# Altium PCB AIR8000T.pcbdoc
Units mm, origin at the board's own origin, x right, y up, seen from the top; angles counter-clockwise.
Board outline 36.51 x 36.8 mm, 2 copper layers (Top Layer, Bottom Layer); 1 components, 0 nets, 104 pads, 0 vias.
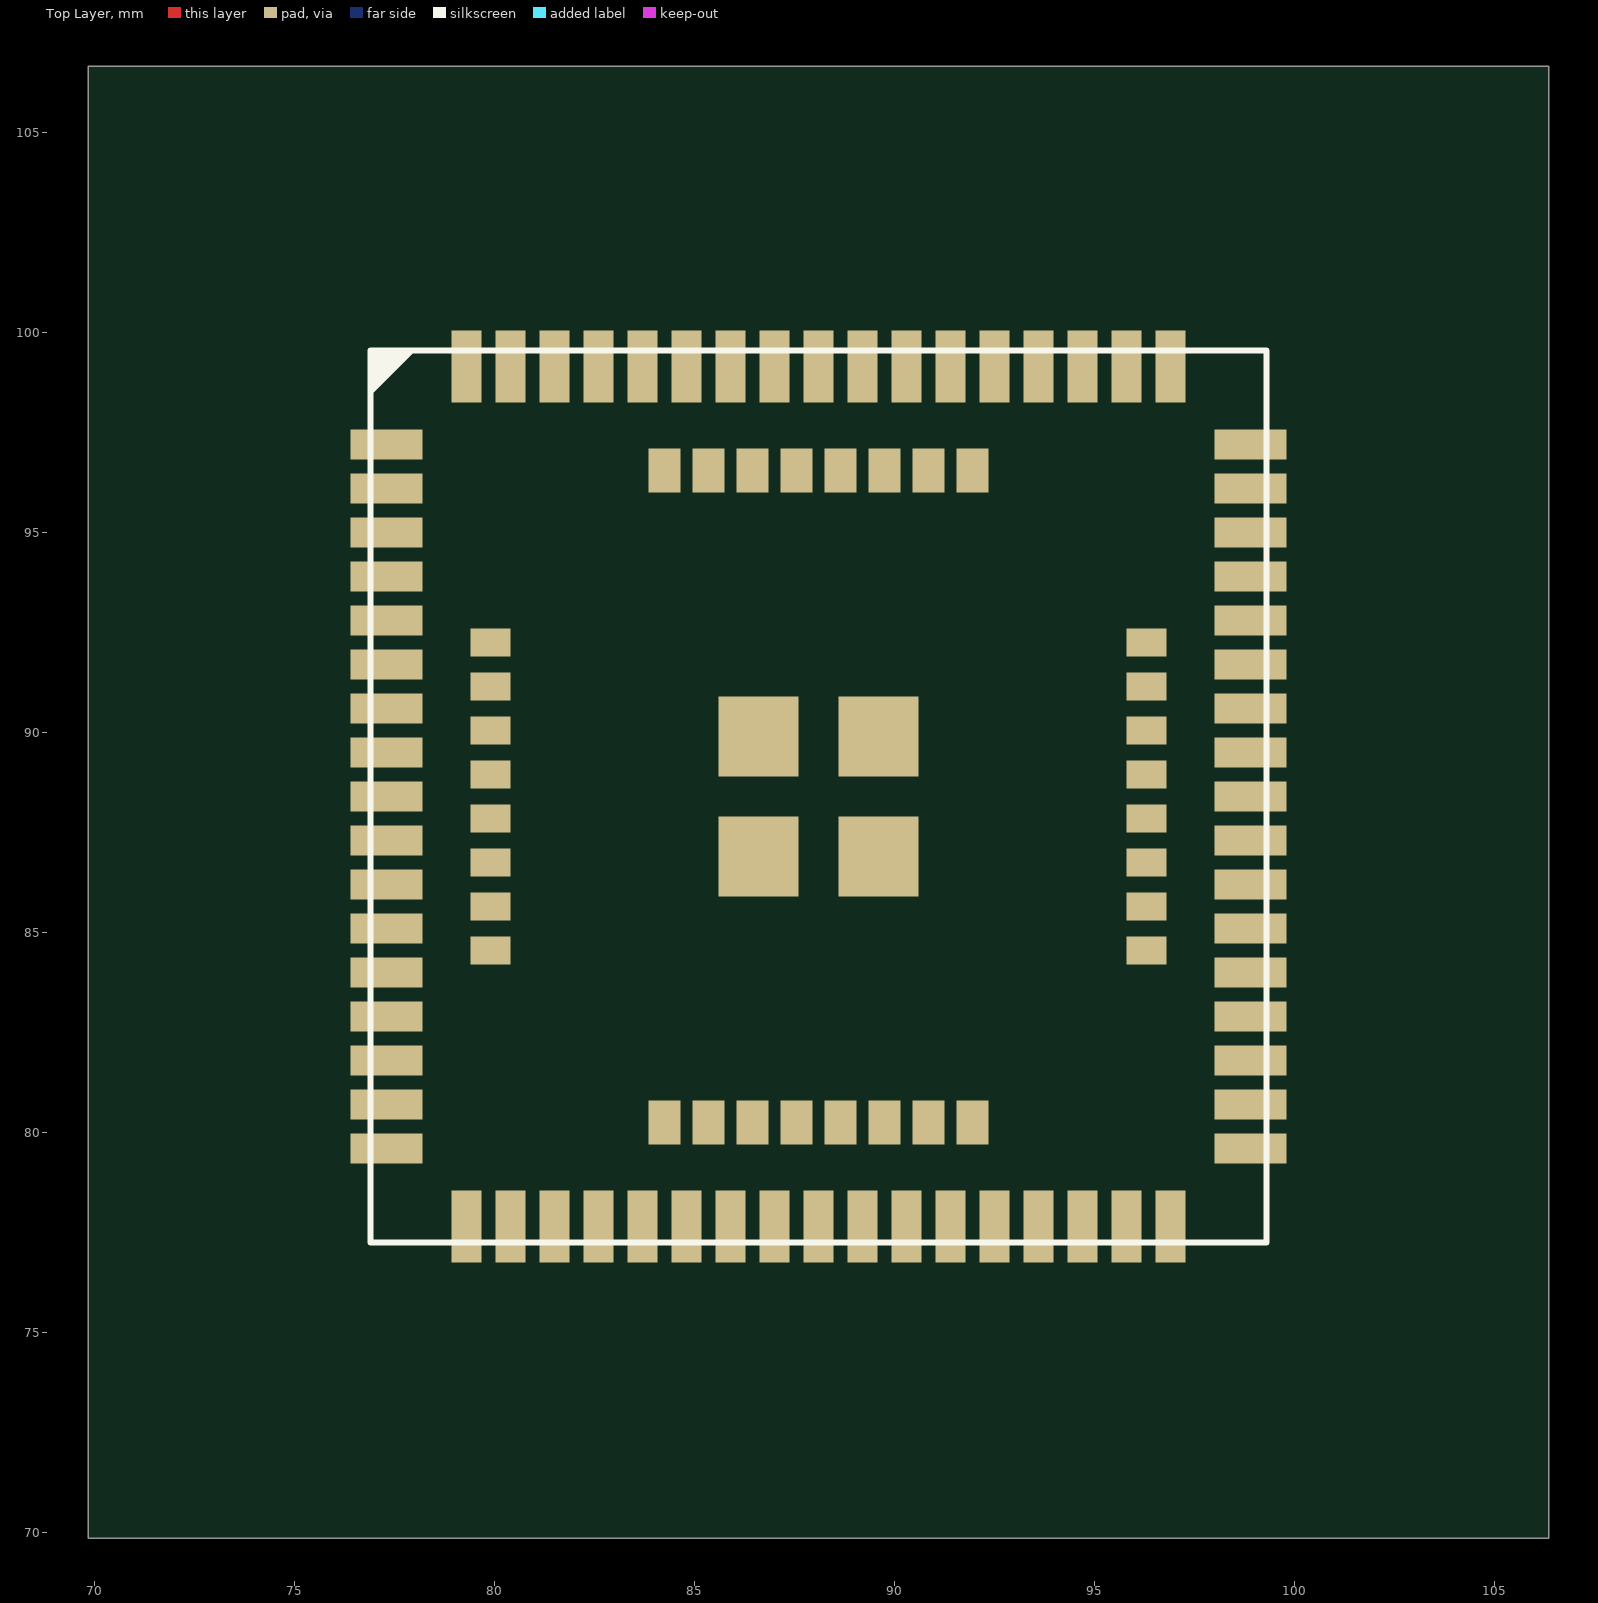
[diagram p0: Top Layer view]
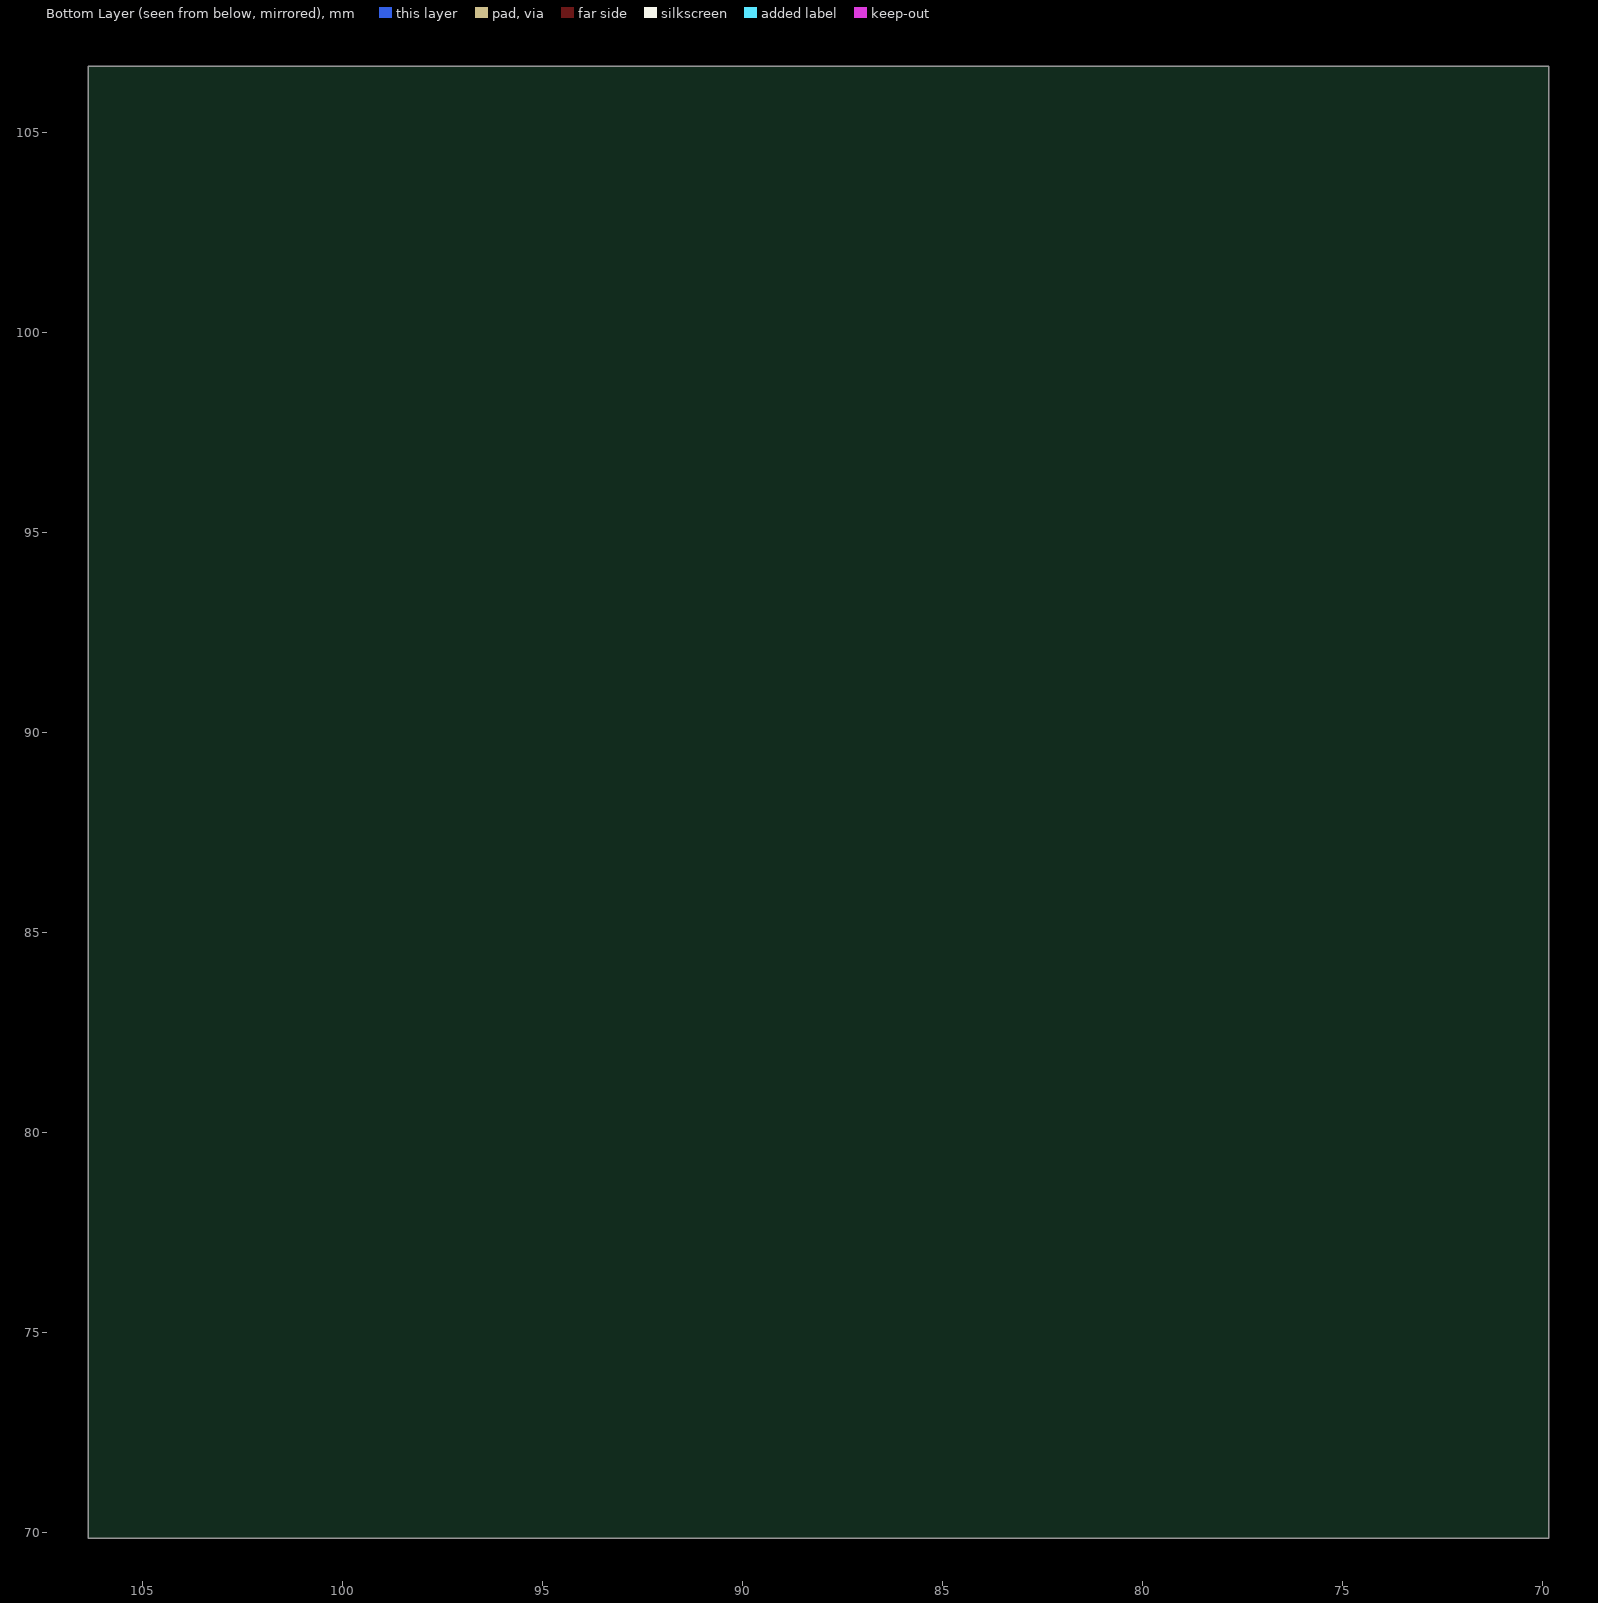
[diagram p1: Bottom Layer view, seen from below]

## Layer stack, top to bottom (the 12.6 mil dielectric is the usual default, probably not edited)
Top Layer: signal copper (thickness not stored)
Dielectric: dielectric 0.32, FR-4, Dk 4.8
Bottom Layer: signal copper (thickness not stored)

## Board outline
106.357,69.85 69.85,69.85 69.85,106.65 106.357,106.65

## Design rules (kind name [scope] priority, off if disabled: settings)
BoardOutlineClearance safeClearance [All] p0: genericclearance=0.254 ignorepadtopadclearanceinfootprint=FALSE except(0: Arc-SplitContinuation Track-SplitContinuation SMDPad-SplitContinuation THPad-SplitContinuation Via-SplitContinuation Fill-SplitContinuation Poly-SplitContinuation Region-SplitContinuation Text-SplitContinuation; 0.152: Track-CutoutEdge SMDPad-CutoutEdge THPad-CutoutEdge Via-CutoutEdge Fill-CutoutEdge Region-CutoutEdge; 0.3: Track-OutlineEdge SMDPad-OutlineEdge THPad-OutlineEdge Via-OutlineEdge Fill-OutlineEdge Region-OutlineEdge Poly-OutlineEdge Text-OutlineEdge)
Clearance safeClearance [All] p1: gap=0.178 ignorepadtopadclearanceinfootprint=FALSE except(0.152: Track-Track Track-SMDPad SMDPad-SMDPad Track-THPad SMDPad-THPad THPad-THPad Track-Via SMDPad-Via THPad-Via Via-Via Track-Fill SMDPad-Fill THPad-Fill Via-Fill Fill-Fill Track-Region SMDPad-Region THPad-Region Via-Region Fill-Region Region-Region Track-Poly SMDPad-Poly THPad-Poly Via-Poly Fill-Poly Region-Poly Poly-Poly Track-Text SMDPad-Text THPad-Text Via-Text Fill-Text Region-Text Poly-Text Text-Text; 0.175: Track-Hole SMDPad-Hole THPad-Hole Via-Hole Fill-Hole Region-Hole Poly-Hole Text-Hole Sheet-Hole; 0.3: Track-Sheet SMDPad-Sheet THPad-Sheet Via-Sheet Fill-Sheet Region-Sheet Poly-Sheet Text-Sheet)
DiffPairsRouting differentialPair [All] p1: maxuncoupledlength=10 minlimit=6 maxlimit=6 mostfreqgap=6 toplayer_minwidth=5 toplayer_prefwidth=10 toplayer_maxwidth=100 bottomlayer_minwidth=5 bottomlayer_prefwidth=10 bottomlayer_maxwidth=100
PasteMaskExpansion pasteMaskExpansion [All] p1: expansion=0
PlaneConnect innerPlane [All] p1: planeconnectstyle=Relief reliefexpansion=0.508 reliefentries=4 reliefconductorwidth=0.254 reliefairgap=0.254
PolygonConnect copperRegion [All] p1: connectstyle=Relief reliefentries=4 reliefconductorwidth=10 polygonreliefangle="90 Angle" airgapwidth=10
RoutingVias viaSize [All] p1: viastyle="Through Hole" holewidth=12.0078 minholewidth=11.811 maxholewidth=236.2204 width=24.0158 minwidth=19.685 maxwidth=393.7008
SolderMaskExpansion solderMaskExpansion [All] p1: useseparateexpansions=TRUE expansion=2 expansionbottom=2
Width trackWidth [All] p1: maxlimit=100 minlimit=5 preferedwidth=10

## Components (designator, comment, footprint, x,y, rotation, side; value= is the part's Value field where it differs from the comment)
? "AIR8000T-PADS" AIR8000T-PADS 88.106,88.401 r0 top

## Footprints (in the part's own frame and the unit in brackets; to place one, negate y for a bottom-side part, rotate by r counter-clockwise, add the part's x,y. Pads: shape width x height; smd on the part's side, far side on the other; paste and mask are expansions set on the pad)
AIR8000T-PADS [mm]
  rect 1.8x0.75 smd: 1(-10.8,8.8) 2(-10.8,7.7) 3(-10.8,6.6) 4(-10.8,5.5) 5(-10.8,4.4) 6(-10.8,3.3) 7(-10.8,2.2) 8(-10.8,1.1) 9(-10.8,0) 10(-10.8,-1.1) 11(-10.8,-2.2) 12(-10.8,-3.3) 13(-10.8,-4.4) 14(-10.8,-5.5) 15(-10.8,-6.6) 16(-10.8,-7.7) 17(-10.8,-8.8) 35(10.8,-8.8) 36(10.8,-7.7) 37(10.8,-6.6) 38(10.8,-5.5) 39(10.8,-4.4) 40(10.8,-3.3) 41(10.8,-2.2) 42(10.8,-1.1) 43(10.8,0) 44(10.8,1.1) 45(10.8,2.2) 46(10.8,3.3) 47(10.8,4.4) 48(10.8,5.5) 49(10.8,6.6) 50(10.8,7.7) 51(10.8,8.8)
  rect 0.75x1.8 smd: 18(-8.8,-10.75) 19(-7.7,-10.75) 20(-6.6,-10.75) 21(-5.5,-10.75) 22(-4.4,-10.75) 23(-3.3,-10.75) 24(-2.2,-10.75) 25(-1.1,-10.75) 26(0,-10.75) 27(1.1,-10.75) 28(2.2,-10.75) 29(3.3,-10.75) 30(4.4,-10.75) 31(5.5,-10.75) 32(6.6,-10.75) 33(7.7,-10.75) 34(8.8,-10.75) 52(8.8,10.75) 53(7.7,10.75) 54(6.6,10.75) 55(5.5,10.75) 56(4.4,10.75) 57(3.3,10.75) 58(2.2,10.75) 59(1.1,10.75) 60(0,10.75) 61(-1.1,10.75) 62(-2.2,10.75) 63(-3.3,10.75) 64(-4.4,10.75) 65(-5.5,10.75) 66(-6.6,10.75) 67(-7.7,10.75) 68(-8.8,10.75)
  rect 1x0.7 smd: 69(-8.2,3.85) 70(-8.2,2.75) 71(-8.2,1.65) 72(-8.2,0.55) 73(-8.2,-0.55) 74(-8.2,-1.65) 75(-8.2,-2.75) 76(-8.2,-3.85) 85(8.2,-3.85) 86(8.2,-2.75) 87(8.2,-1.65) 88(8.2,-0.55) 89(8.2,0.55) 90(8.2,1.65) 91(8.2,2.75) 92(8.2,3.85)
  rect 0.8x1.1 smd: 77(-3.85,-8.15) 78(-2.75,-8.15) 79(-1.65,-8.15) 80(-0.55,-8.15) 81(0.55,-8.15) 82(1.65,-8.15) 83(2.75,-8.15) 84(3.85,-8.15) 93(3.85,8.15) 94(2.75,8.15) 95(1.65,8.15) 96(0.55,8.15) 97(-0.55,8.15) 98(-1.65,8.15) 99(-2.75,8.15) 100(-3.85,8.15)
  rect 2x2 smd: 101(-1.5,1.5) 102(-1.5,-1.5) 103(1.5,-1.5) 104(1.5,1.5)
  silkscreen extent -11.22,-11.15 11.2,11.15

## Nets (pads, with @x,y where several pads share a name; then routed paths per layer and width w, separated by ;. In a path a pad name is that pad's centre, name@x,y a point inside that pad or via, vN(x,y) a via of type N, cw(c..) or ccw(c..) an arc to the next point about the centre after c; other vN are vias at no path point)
pads on no net: ?.1 ?.2 ?.3 ?.4 ?.5 ?.6 ?.7 ?.8 ?.9 ?.10 ?.11 ?.12 ?.13 ?.14 ?.15 ?.16 ?.17 ?.18 ?.19 ?.20 ?.21 ?.22 ?.23 ?.24 ?.25 ?.26 ?.27 ?.28 ?.29 ?.30 ?.31 ?.32 ?.33 ?.34 ?.35 ?.36 ?.37 ?.38 ?.39 ?.40 ?.41 ?.42 ?.43 ?.44 ?.45 ?.46 ?.47 ?.48 ?.49 ?.50 ?.51 ?.52 ?.53 ?.54 ?.55 ?.56 ?.57 ?.58 ?.59 ?.60 ?.61 ?.62 ?.63 ?.64 ?.65 ?.66 ?.67 ?.68 ?.69 ?.70 ?.71 ?.72 ?.73 ?.74 ?.75 ?.76 ?.77 ?.78 ?.79 ?.80 ?.81 ?.82 ?.83 ?.84 ?.85 ?.86 ?.87 ?.88 ?.89 ?.90 ?.91 ?.92 ?.93 ?.94 ?.95 ?.96 ?.97 ?.98 ?.99 ?.100 ?.101 ?.102 ?.103 ?.104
